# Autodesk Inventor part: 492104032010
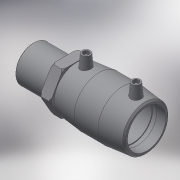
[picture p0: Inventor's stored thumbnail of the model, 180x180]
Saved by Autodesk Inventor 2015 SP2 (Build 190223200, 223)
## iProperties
Created: 2017-06
Part Number: 492104032010
Material: Generic
Description: PLASSON Male Transition Coupler 32 x 1"
Document SubType Name: Modeling
Designer: KIM
Mass: 92.4938 g
Surface Area: 328.275 cm^2
Volume: 92.4938 cm^3
Density: 1 g/cm^3
Appearance: Default
Author: KIM
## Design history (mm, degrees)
derived "492104.ipt"
feature "Solid1::492104.ipt"
tag "TaggingFeature1"
body "Solid1"
other parameters: "d0" = 88, "d1" = 32, "d2" = 44, "d3" = 42, "d4" = 29.33333, "d5" = 39.6, "d6" = 30.4, "d7" = 32, "d8" = 168 deg, "d10" = 16.8, "d11" = 5.6, "d29" = 42, "d30" = 14, "d31" = 30.8, "d34" = 5 deg, "d41" = 4, "d42" = 14, "d43" = 0, "d48" = 3, "d49" = 0, "d57" = 23, "d58" = 33.249, "d59" = 26.5992, "d60" = 30.6, "d61" = 44, "d62" = 0.66498, "d65" = 1.32, "d70" = 0.1, "d71" = 34, "d72" = 8.5, "d73" = 16.8, "d75" = 0, "d_" = 32, "L_" = 122, "L_1" = 42, "D_1" = 44, "A_" = 42, "d_2" = 12, "L_2" = 34, "D_" = 23, "R_" = 33.249
